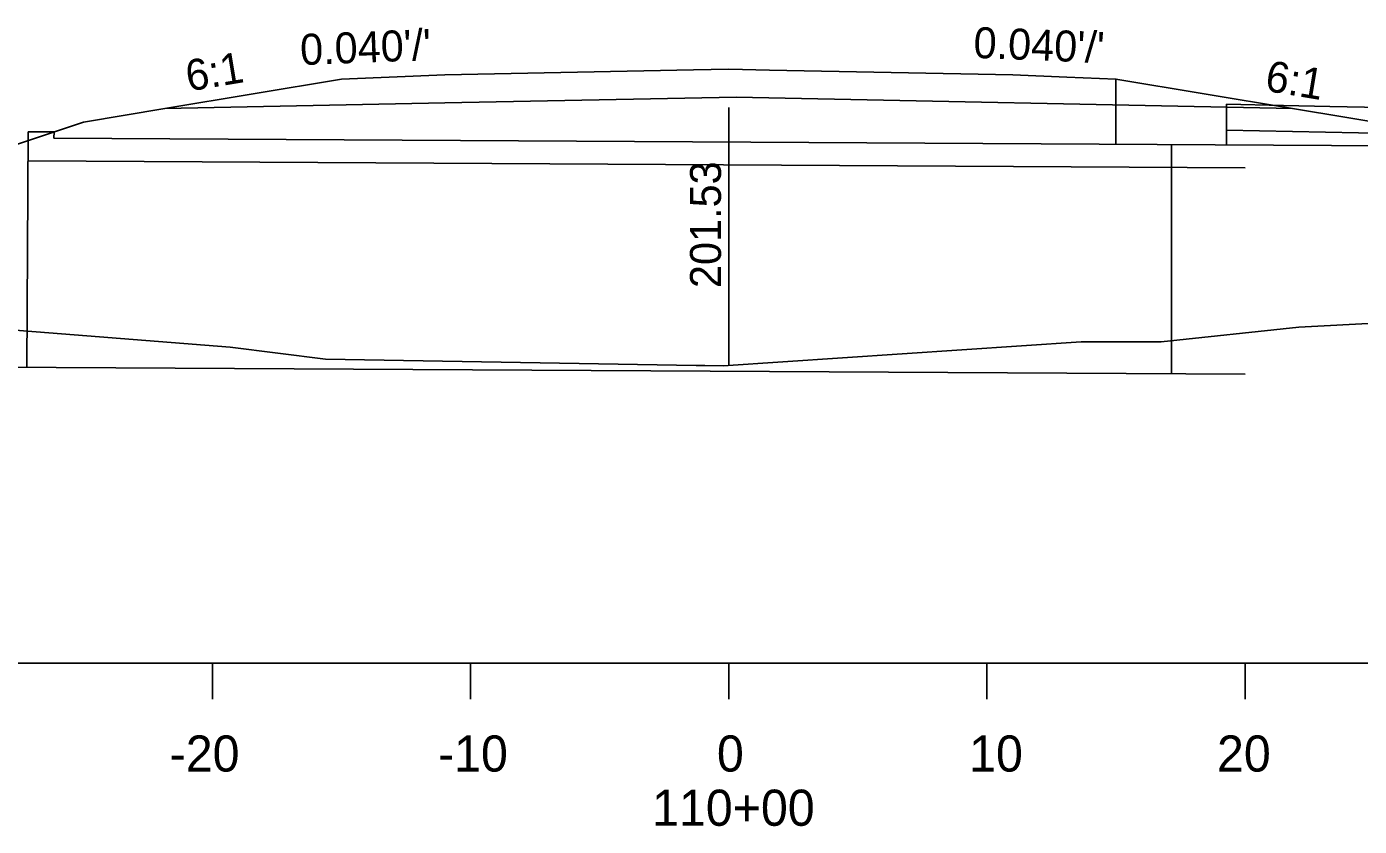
# Model space of a CAD drawing. Extents: x 2829243 to 2838161, y 467639 to 474695.
# Drawn here: x 2832036 to 2832294.1, y 469938.7 to 470093.6 of the extents above; entities that cross this region are included whole.
import ezdxf

# ---------------------------------------------------------------- set-up
doc = ezdxf.new("R2010")
doc.units = 0
for name, color, linetype in [('R_Alt Surface', 7, 'Continuous'), ('R_Axis', 7, 'Continuous'), ('R_Axis Annot', 7, 'Continuous'), ('R_Detour', 7, 'Continuous'), ('R_Exist Surface', 7, 'Continuous'), ('R_Fin Surface', 7, 'Continuous'), ('R_Water', 7, 'Continuous'), ('R_Xsect Elev', 7, 'Continuous'), ('R_Xsect Slope', 7, 'Continuous')]:
    doc.layers.add(name, color=color, linetype=linetype)

msp = doc.modelspace()

# ---------------------------------------------------------------- linework, layer by layer
at = {"layer": 'R_Alt Surface'}
for points in [[(2832062.75, 470077.71), (2832116.96, 470078.8), (2832173.4, 470079.87), (2832281.16, 470077.71)], [(2832268.39, 470073.52), (2832325.89, 470072.37), (2832389.35, 470071.1)]]:
    msp.add_lwpolyline(points, dxfattribs=at)
at = {"layer": 'R_Axis'}
for p, q in [((2831421.96, 469970.29), (2832921.96, 469970.29)), ((2832071.96, 469963.29), (2832071.96, 469970.29)), ((2832121.96, 469963.29), (2832121.96, 469970.29)), ((2832171.96, 469963.29), (2832171.96, 469970.29)), ((2832221.96, 469963.29), (2832221.96, 469970.29)), ((2832271.96, 469963.29), (2832271.96, 469970.29))]:
    msp.add_line(p, q, dxfattribs=at)
at = {"layer": 'R_Detour'}
for p, q in [((2832246.96, 470083.41), (2832246.96, 470070.77)), ((2832268.39, 470078.52), (2832268.39, 470070.65))]:
    msp.add_line(p, q, dxfattribs=at)
msp.add_lwpolyline([(2832268.39, 470078.52), (2832279.4, 470078.3), (2832288.39, 470078.12), (2832305.24, 470077.79), (2832325.89, 470077.37), (2832342.73, 470077.04), (2832363.39, 470076.62), (2832368.9, 470076.51), (2832373.39, 470076.42), (2832380.55, 470074.04), (2832389.35, 470071.1), (2832466.05, 470045.54), (2832528.3, 470024.79), (2832581.64, 470042.56), (2832716.63, 470088.59), (2832723.46, 470090.52), (2832731.53, 470092.77)], dxfattribs=at)
at = {"layer": 'R_Exist Surface'}
msp.add_lwpolyline([(2831891.2, 470066.21), (2831923.92, 470058.94), (2832009.96, 470036.62), (2832045.14, 470033.88), (2832075.41, 470031.51), (2832093.85, 470029.19), (2832165.67, 470027.94), (2832167.32, 470027.92), (2832170.89, 470027.85), (2832240.25, 470032.54), (2832255.72, 470032.55), (2832282.38, 470035.38), (2832330.03, 470037.9), (2832343.03, 470037.95), (2832345.71, 470038), (2832355.82, 470041.63), (2832425.43, 470055.06), (2832491.03, 470069.51), (2832499.96, 470071.51), (2832513.84, 470074.54), (2832570.91, 470076.45)], dxfattribs=at)
at = {"layer": 'R_Fin Surface'}
msp.add_lwpolyline([(2831789.07, 470067.46), (2831789.07, 470067.45), (2831906.59, 470028.29), (2832046.96, 470075.08), (2832062.75, 470077.71), (2832096.96, 470083.41), (2832116.96, 470084.21), (2832165.15, 470085.17), (2832171.96, 470085.31), (2832179.86, 470085.15), (2832226.96, 470084.21), (2832237.43, 470083.79), (2832246.96, 470083.41), (2832281.16, 470077.71), (2832311.96, 470072.58), (2832389.58, 470071.03)], dxfattribs=at)
at = {"layer": 'R_Water'}
for p, q in [((2832036.01, 470027.56), (2832036.27, 470073.21)), ((2832036.27, 470073.21), (2832041.27, 470073.18)), ((2832041.27, 470073.18), (2832041.26, 470071.93)), ((2832041.26, 470071.93), (2832392.81, 470069.95)), ((2832257.69, 470026.31), (2832257.69, 470070.71)), ((2832036.24, 470067.56), (2832271.96, 470066.23)), ((2831906.59, 470028.29), (2832271.96, 470026.23))]:
    msp.add_line(p, q, dxfattribs=at)
at = {"layer": 'R_Xsect Elev'}
msp.add_line((2832171.96, 470027.93), (2832171.96, 470077.93), dxfattribs=at)

# ---------------------------------------------------------------- texts
at = {"layer": 'R_Axis Annot'}
for s, p in [('-20', (2832063.67, 469949.29)), ('-10', (2832115.65, 469949.29)), ('0', (2832169.67, 469949.29)), ('10', (2832218.52, 469949.29)), ('20', (2832266.53, 469949.29)), ('110+00', (2832157.11, 469938.79))]:
    msp.add_text(s, height=7, dxfattribs=at).set_placement(p)
at = {"layer": 'R_Xsect Elev'}
msp.add_text('201.53', height=6, rotation=90, dxfattribs=at).set_placement((2832170.46, 470042.93))
at = {"layer": 'R_Xsect Slope'}
for s, rotation, p in [("0.040'/'", 2.2902, (2832089.05, 470086.1)), ("0.040'/'", 357.7094, (2832219.28, 470087.52)), ('6:1', 9.4648, (2832067.31, 470081)), ('6:1', 350.5368, (2832275.63, 470081.17))]:
    msp.add_text(s, height=6, rotation=rotation, dxfattribs=at).set_placement(p)

doc.saveas('drawing.dxf')
